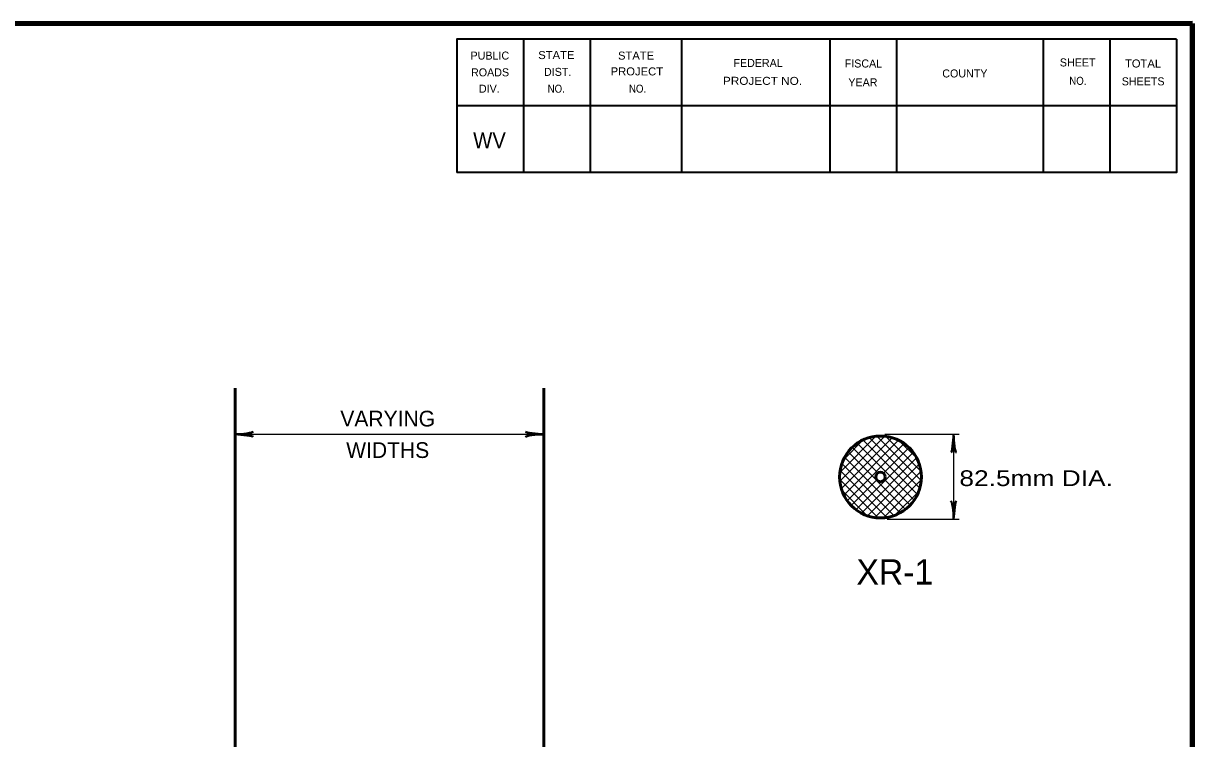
# Model space of a CAD drawing. Extents: x -1843 to -987, y 1073 to 1617.
# Drawn here: x -1216.6 to -993.8, y 1474.2 to 1610.4 of the extents above; entities that cross this region are included whole.
import ezdxf
from ezdxf.enums import TextEntityAlignment as Align

# ---------------------------------------------------------------- set-up
doc = ezdxf.new("R2010")
doc.units = 0
doc.header["$LTSCALE"] = 1.2
doc.layers.add('1', color=7, linetype='Continuous', lineweight=53)
doc.layers.add('61', color=7, linetype='Continuous', lineweight=35)

msp = doc.modelspace()

# ---------------------------------------------------------------- linework, layer by layer
at = {"layer": '1', "lineweight": 158}
msp.add_line((-993.822, 1084.318), (-993.822, 1610.418), dxfattribs=at)
at = {"layer": '1', "lineweight": 13}
msp.add_line((-993.822, 1084.318), (-993.822, 1610.418), dxfattribs=at)
at = {"layer": '1'}
for p, q in [((-1176.264, 1459.339), (-1176.264, 1540.942)), ((-1117.464, 1459.339), (-1117.464, 1540.942))]:
    msp.add_line(p, q, dxfattribs=at)
at = {"layer": '1', "lineweight": 25}
for p, q in [((-1176.276, 1532.134), (-1117.464, 1532.134)), ((-1061.06, 1523.178), (-1052.475, 1531.763)), ((-1061.055, 1524.88), (-1054.177, 1531.758)), ((-1060.775, 1521.766), (-1051.063, 1531.478)), ((-1060.411, 1527.222), (-1056.518, 1531.114)), ((-1060.295, 1520.549), (-1049.846, 1530.999)), ((-1046.265, 1520.647), (-1056.664, 1531.047)), ((-1045.8, 1521.88), (-1055.432, 1531.511)), ((-1045.535, 1523.312), (-1053.999, 1531.776)), ((-1052.501, 1532.172), (-1038.309, 1532.172)), ((-1045.574, 1525.047), (-1052.264, 1531.738)), ((-1046.33, 1527.501), (-1049.81, 1530.981)), ((-1039.365, 1532.106), (-1039.365, 1515.977)), ((-1059.66, 1519.487), (-1048.783, 1530.364)), ((-1048.54, 1517.831), (-1059.48, 1528.771)), ((-1053.74, 1524.728), (-1058.675, 1529.663)), ((-1057.985, 1517.768), (-1047.065, 1528.688)), ((-1046.887, 1519.573), (-1057.739, 1530.424)), ((-1052.759, 1524.692), (-1047.859, 1529.592)), ((-1050.743, 1516.64), (-1060.671, 1526.569)), ((-1049.567, 1517.161), (-1060.15, 1527.745)), ((-1056.946, 1517.11), (-1046.407, 1527.649)), ((-1055.756, 1516.603), (-1045.899, 1526.459)), ((-1052.1, 1516.301), (-1061.011, 1525.211)), ((-1054.38, 1516.282), (-1045.579, 1525.083)), ((-1053.715, 1516.218), (-1061.093, 1523.597)), ((-1058.888, 1518.562), (-1054.021, 1523.429)), ((-1052.737, 1516.228), (-1045.525, 1523.44)), ((-1047.648, 1518.636), (-1052.568, 1523.557)), ((-1055.817, 1516.623), (-1060.688, 1521.494)), ((-1050.563, 1516.705), (-1046.002, 1521.266)), ((-1052.039, 1515.977), (-1038.309, 1515.977))]:
    msp.add_line(p, q, dxfattribs=at)
at = {"layer": '1', "lineweight": 158}
msp.add_lwpolyline([(-993.822, 1610.418), (-1785.522, 1610.318), (-1785.422, 1084.318)], dxfattribs=at)
at = {"layer": '1'}
for radius in [7.8, 0.9]:
    msp.add_circle((-1053.304, 1524.007), radius, dxfattribs=at)
at = {"layer": '1', "lineweight": 40}
for centre, major_axis, ratio, start_param, end_param in [((-1174.931, 1531.88), (2.108, -0.211), 0.07063, 6.2823074, 8.5597026), ((-1174.966, 1532.466), (-2.143, -0.187), 0.122415, 0.8963533, 3.1415927), ((-1118.773, 1531.803), (2.143, 0.187), 0.122415, 0.8963533, 3.1415927), ((-1118.808, 1532.388), (2.108, -0.211), 0.07063, 3.1407148, 5.41811), ((-1039.619, 1530.761), (-0.211, -2.108), 0.07063, 6.2823074, 8.5597026), ((-1039.034, 1530.796), (-0.187, 2.143), 0.122415, 0.8963533, 3.1415927), ((-1039.697, 1517.287), (0.187, -2.143), 0.122415, 0.8963533, 3.1415927), ((-1039.111, 1517.322), (0.211, 2.108), 0.07063, 6.2823074, 8.5597026)]:
    msp.add_ellipse(centre, major_axis=major_axis, ratio=ratio, start_param=start_param, end_param=end_param, dxfattribs=at)
at = {"layer": '61'}
for p, q in [((-1121.322, 1607.418), (-1121.322, 1582.018)), ((-1108.621, 1607.418), (-1108.621, 1582.018)), ((-1091.222, 1607.418), (-1091.222, 1582.018)), ((-1062.922, 1607.418), (-1062.922, 1582.018)), ((-1050.222, 1607.418), (-1050.222, 1582.018)), ((-1022.322, 1607.418), (-1022.322, 1582.018)), ((-1009.622, 1607.418), (-1009.622, 1582.018)), ((-996.922, 1594.717), (-1134.022, 1594.717))]:
    msp.add_line(p, q, dxfattribs=at)
for points in [[(-996.922, 1607.418), (-1134.022, 1607.418), (-1134.022, 1582.018)], [(-996.922, 1607.418), (-996.922, 1582.018), (-1134.022, 1582.018)]]:
    msp.add_lwpolyline(points, dxfattribs=at)

# ---------------------------------------------------------------- texts
at = {"layer": '1', "width": 0.95}
msp.add_text('WV', height=3.048, dxfattribs=at).set_placement((-1130.922, 1586.618))
at = {"layer": '1'}
for s, height, p in [('VARYING', 3, (-1147.205, 1533.624)), ('WIDTHS', 3, (-1147.205, 1527.624)), ('XR-1', 4.8, (-1050.573, 1503.513))]:
    msp.add_text(s, height=height, dxfattribs=at).set_placement(p, align=Align.CENTER)
at = {"layer": '1', "width": 1.25}
msp.add_text('82.5mm DIA.', height=3, dxfattribs=at).set_placement((-1023.639, 1522.269), align=Align.CENTER)
at = {"layer": '61'}
for s, height, rotation, p in [('PUBLIC', 1.525, 0.033, (-1131.422, 1603.518)), ('FEDERAL', 1.523, 0.007, (-1081.322, 1602.118)), ('FISCAL', 1.525, 359.942, (-1060.121, 1602.018)), ('SHEET', 1.525, 0.059, (-1019.122, 1602.217)), ('ROADS', 1.525, 0.124, (-1131.322, 1600.318)), ('DIST.', 1.525, 0.056, (-1117.422, 1600.418)), ('YEAR', 1.523, 0.105, (-1059.422, 1598.418)), ('COUNTY', 1.523, 0.069, (-1041.522, 1600.118)), ('SHEETS', 1.523, 359.959, (-1007.322, 1598.618)), ('DIV.', 1.525, 359.932, (-1129.822, 1597.217))]:
    msp.add_text(s, height=height, rotation=rotation, dxfattribs=at).set_placement(p)
for s, rotation, width, p in [('STATE', 0.059, 1.05, (-1118.522, 1603.618)), ('STATE', 0.059, 1.05, (-1103.322, 1603.518)), ('PROJECT', 359.908, 1.05, (-1104.722, 1600.518)), ('TOTAL', 359.926, 1.05, (-1006.721, 1602.018)), ('PROJECT NO.', 359.922, 1.1, (-1083.322, 1598.717)), ('NO.', 359.852, 0.9, (-1017.322, 1598.717)), ('NO.', 359.852, 0.9, (-1116.722, 1597.217)), ('NO.', 0.225, 0.9, (-1101.222, 1597.217))]:
    msp.add_text(s, height=1.525, rotation=rotation, dxfattribs=dict(at, width=width)).set_placement(p)

doc.saveas('drawing.dxf')
